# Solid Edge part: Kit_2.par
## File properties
Sűrűség: 0,000 kg/m^3
Pontosság: 0,990
Author: ahadarics
Last saved by: ahadarics
Revision: 76
Username: ahadarics
Dokumentum tartalom típus: 0
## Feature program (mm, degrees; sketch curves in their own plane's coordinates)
base feature "unnamed BaseFeature 1"
sketch for "unnamed Hole 1" plane through (-23.25, 23.25, 5) normal (0, 0, -1) x-axis (0, -1, 0)
  hole centre (0, 0) bore radius 3.3235
hole "unnamed Hole 1" through
sketch for "unnamed Hole 2" plane through (-23.25, 23.25, 5) normal (0, 0, -1) x-axis (0, -1, 0)
  hole centre (46.5, 0) bore radius 3.3235
hole "unnamed Hole 2" through
sketch for "unnamed Hole 3" plane through (-23.25, 23.25, 5) normal (0, 0, -1) x-axis (0, -1, 0)
  hole centre (46.5, -46.5) bore radius 3.3235
hole "unnamed Hole 3" through
sketch for "unnamed Hole 4" plane through (-23.25, 23.25, 5) normal (0, 0, -1) x-axis (0, -1, 0)
  hole centre (0, -46.5) bore radius 3.3235
hole "unnamed Hole 4" through
pattern "unnamed Pattern 1" of "unnamed Hole 1", "unnamed Hole 2", "unnamed Hole 3", "unnamed Hole 4"
sketch for "Furat_5" plane through (-32.6867, 0, 7.25) normal (-0.999962, 0, -0.008727) x-axis (0, -1, 0)
  hole centre (0.0006, 0.7497) bore radius 4.283
  dimension (linear) = 0.0006
hole "Furat_5" diameter 8.566 finite
thread "unnamed Thread 1"
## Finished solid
Body 1: solid body, 302 faces, 736 edges, 454 vertices, 4 internal voids.
  Faces by surface: plane 139, cylinder 78, swept 53, torus 20, cone 11, spline 1
  Edges by curve: line 413, circle 160, spline 118, ellipse 28, curve on surface 17
Bounding box of the edges (mm; curved faces can reach further): 65.500 x 65.500 x 14.500, from (-32.75, -32.75, 0) to (32.75, 32.75, 14.5).
Cylindrical faces by radius (mm): R0.2 x40, R0.201 x2, R0.2012 x2, R2.5402 x12, R2.6 x4, R3.3235 x4, R3.75 x4, R3.85 x4, R4.283 x1, R5.25 x4, R6 x1
Conical faces (half-angle, radius in mm at the cone's reference point): 0.5 deg R6.5 x2, 0.5 deg R8 x4, 45 deg R3.6735 x4, 45 deg R6.15 x1
Toroidal faces (ring radius, tube radius in mm): R2.9402 r0.4 x12, R3.55 r0.2 x8
Planar faces by outward normal: +x 11, +y 12, +z 1, -x 12, -y 12, -z 22, oblique 69
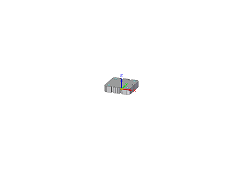
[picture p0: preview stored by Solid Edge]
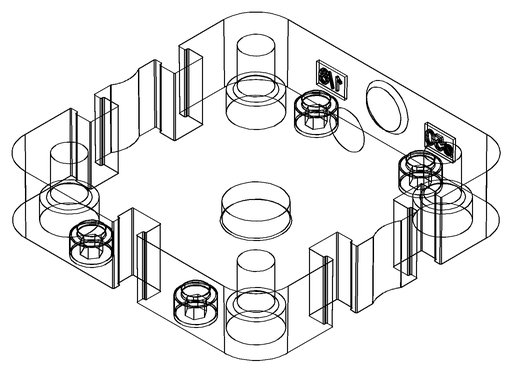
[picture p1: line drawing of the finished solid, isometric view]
